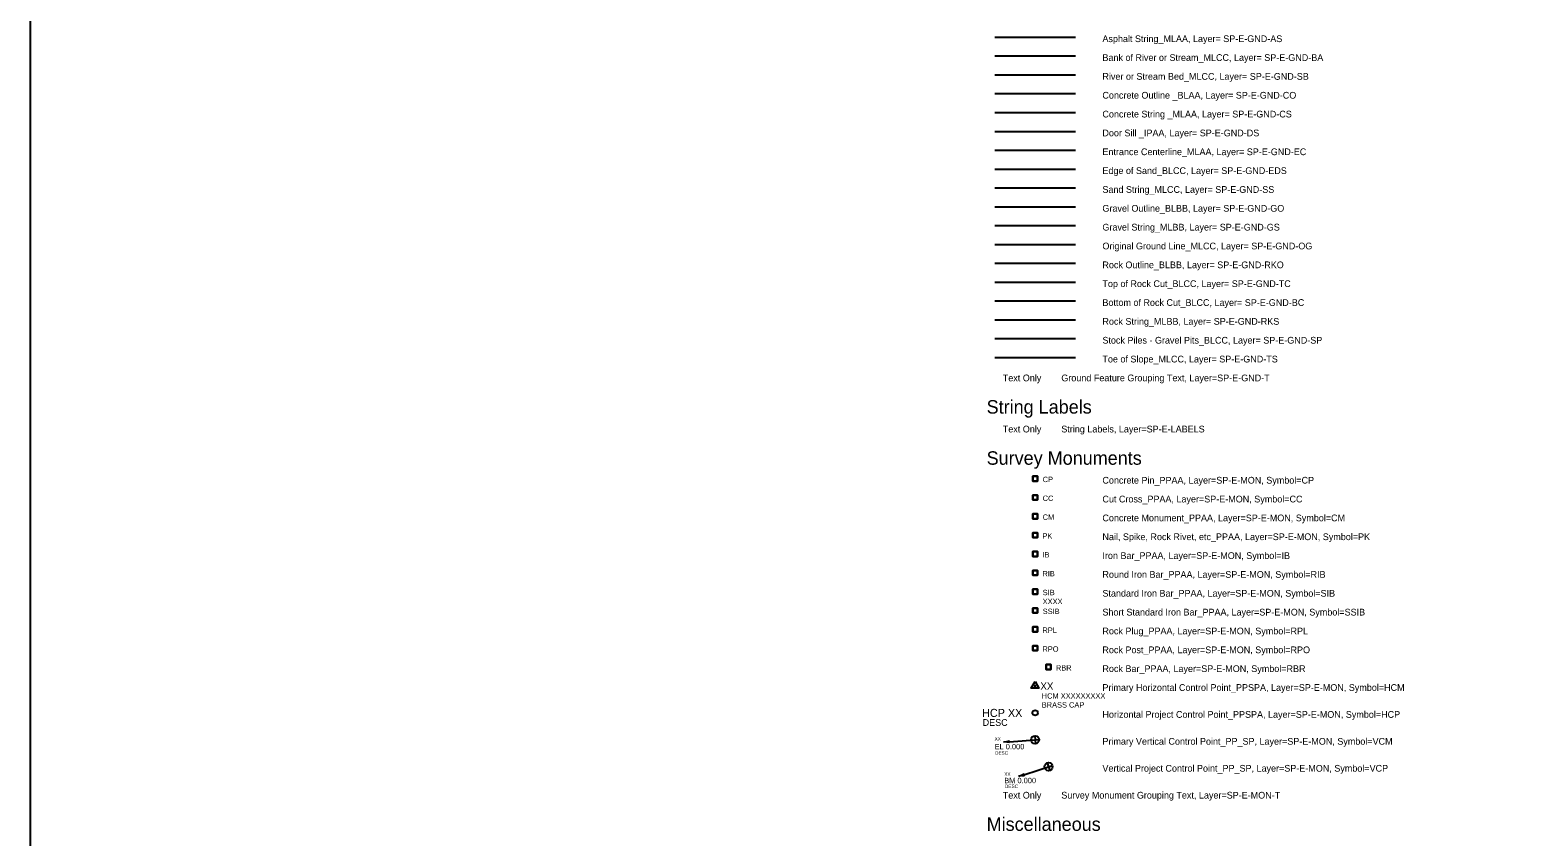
# Model space of a CAD drawing. Extents: x 500528 to 502626, y 4210261 to 4212624.
# Drawn here: x 500528 to 501088, y 4211729 to 4212028 of the extents above; entities that cross this region are included whole.
import ezdxf

# ---------------------------------------------------------------- set-up
doc = ezdxf.new("R2010")
doc.units = 0
for name, color, linetype in [('Default', 7, 'Continuous'), ('SP-E-GND-AS', 7, 'Continuous'), ('SP-E-GND-BA', 7, 'Continuous'), ('SP-E-GND-BC', 7, 'Continuous'), ('SP-E-GND-CO', 7, 'Continuous'), ('SP-E-GND-CS', 7, 'Continuous'), ('SP-E-GND-DS', 7, 'Continuous'), ('SP-E-GND-EC', 7, 'Continuous'), ('SP-E-GND-EDS', 7, 'Continuous'), ('SP-E-GND-GO', 7, 'Continuous'), ('SP-E-GND-GS', 7, 'Continuous'), ('SP-E-GND-OG', 7, 'Continuous'), ('SP-E-GND-RKO', 7, 'Continuous'), ('SP-E-GND-RKS', 7, 'Continuous'), ('SP-E-GND-SB', 7, 'Continuous'), ('SP-E-GND-SP', 7, 'Continuous'), ('SP-E-GND-SS', 7, 'Continuous'), ('SP-E-GND-T', 7, 'Continuous'), ('SP-E-GND-TC', 7, 'Continuous'), ('SP-E-GND-TS', 7, 'Continuous'), ('SP-E-LABELS', 7, 'Continuous'), ('SP-E-MON', 7, 'Continuous'), ('SP-E-MON-T', 7, 'Continuous')]:
    doc.layers.add(name, color=color, linetype=linetype)

# ---------------------------------------------------------------- blocks, each defined once
blk = doc.blocks.new('CP')
at = {"layer": 'SP-E-MON'}
for points in [[(-0.09, 0.09), (0.09, 0.09), (0.09, -0.09), (-0.09, -0.09), (-0.09, 0.09)], [(0.09, -0.09), (0.09, 0.09), (-0.09, 0.09), (-0.09, -0.09), (0.09, -0.09)]]:
    blk.add_lwpolyline(points, dxfattribs=at)
at = {"layer": 'SP-E-MON-T'}
blk.add_text('CP', height=0.2, dxfattribs=at).set_placement((0.281, -0.13))
blk = doc.blocks.new('CC')
at = {"layer": 'SP-E-MON'}
for points in [[(-0.09, 0.09), (0.09, 0.09), (0.09, -0.09), (-0.09, -0.09), (-0.09, 0.09)], [(0.09, -0.09), (0.09, 0.09), (-0.09, 0.09), (-0.09, -0.09), (0.09, -0.09)]]:
    blk.add_lwpolyline(points, dxfattribs=at)
at = {"layer": 'SP-E-MON-T'}
blk.add_text('CC', height=0.2, dxfattribs=at).set_placement((0.281, -0.13))
blk = doc.blocks.new('CM')
at = {"layer": 'SP-E-MON'}
for points in [[(-0.09, 0.09), (0.09, 0.09), (0.09, -0.09), (-0.09, -0.09), (-0.09, 0.09)], [(0.09, -0.09), (0.09, 0.09), (-0.09, 0.09), (-0.09, -0.09), (0.09, -0.09)]]:
    blk.add_lwpolyline(points, dxfattribs=at)
at = {"layer": 'SP-E-MON-T'}
blk.add_text('CM', height=0.2, dxfattribs=at).set_placement((0.281, -0.13))
blk = doc.blocks.new('PK')
at = {"layer": 'SP-E-MON'}
for points in [[(-0.09, 0.09), (0.09, 0.09), (0.09, -0.09), (-0.09, -0.09), (-0.09, 0.09)], [(0.09, -0.09), (0.09, 0.09), (-0.09, 0.09), (-0.09, -0.09), (0.09, -0.09)]]:
    blk.add_lwpolyline(points, dxfattribs=at)
at = {"layer": 'SP-E-MON-T'}
blk.add_text('PK', height=0.2, dxfattribs=at).set_placement((0.272, -0.13))
blk = doc.blocks.new('IB')
at = {"layer": 'SP-E-MON'}
for points in [[(-0.09, 0.09), (0.09, 0.09), (0.09, -0.09), (-0.09, -0.09), (-0.09, 0.09)], [(0.09, -0.09), (0.09, 0.09), (-0.09, 0.09), (-0.09, -0.09), (0.09, -0.09)]]:
    blk.add_lwpolyline(points, dxfattribs=at)
at = {"layer": 'SP-E-MON-T'}
blk.add_text('IB', height=0.2, dxfattribs=at).set_placement((0.272, -0.13))
blk = doc.blocks.new('RIB')
at = {"layer": 'SP-E-MON'}
for points in [[(-0.09, 0.09), (0.09, 0.09), (0.09, -0.09), (-0.09, -0.09), (-0.09, 0.09)], [(0.09, -0.09), (0.09, 0.09), (-0.09, 0.09), (-0.09, -0.09), (0.09, -0.09)]]:
    blk.add_lwpolyline(points, dxfattribs=at)
at = {"layer": 'SP-E-MON-T'}
blk.add_text('RIB', height=0.2, dxfattribs=at).set_placement((0.272, -0.13))
blk = doc.blocks.new('SIB')
at = {"layer": 'SP-E-MON'}
for points in [[(-0.09, 0.09), (0.09, 0.09), (0.09, -0.09), (-0.09, -0.09), (-0.09, 0.09)], [(0.09, -0.09), (0.09, 0.09), (-0.09, 0.09), (-0.09, -0.09), (0.09, -0.09)]]:
    blk.add_lwpolyline(points, dxfattribs=at)
at = {"layer": 'SP-E-MON-T'}
for s, p in [('SIB', (0.281, -0.13)), ('XXXX', (0.281, -0.463))]:
    blk.add_text(s, height=0.2, dxfattribs=at).set_placement(p)
blk = doc.blocks.new('SSIB')
at = {"layer": 'SP-E-MON'}
for points in [[(-0.09, 0.09), (0.09, 0.09), (0.09, -0.09), (-0.09, -0.09), (-0.09, 0.09)], [(0.09, -0.09), (0.09, 0.09), (-0.09, 0.09), (-0.09, -0.09), (0.09, -0.09)]]:
    blk.add_lwpolyline(points, dxfattribs=at)
at = {"layer": 'SP-E-MON-T'}
blk.add_text('SSIB', height=0.2, dxfattribs=at).set_placement((0.281, -0.13))
blk = doc.blocks.new('RPL')
at = {"layer": 'SP-E-MON'}
for points in [[(-0.09, 0.09), (0.09, 0.09), (0.09, -0.09), (-0.09, -0.09), (-0.09, 0.09)], [(0.09, -0.09), (0.09, 0.09), (-0.09, 0.09), (-0.09, -0.09), (0.09, -0.09)]]:
    blk.add_lwpolyline(points, dxfattribs=at)
at = {"layer": 'SP-E-MON-T'}
blk.add_text('RPL', height=0.2, dxfattribs=at).set_placement((0.272, -0.13))
blk = doc.blocks.new('RPO')
at = {"layer": 'SP-E-MON'}
for points in [[(-0.09, 0.09), (0.09, 0.09), (0.09, -0.09), (-0.09, -0.09), (-0.09, 0.09)], [(0.09, -0.09), (0.09, 0.09), (-0.09, 0.09), (-0.09, -0.09), (0.09, -0.09)]]:
    blk.add_lwpolyline(points, dxfattribs=at)
at = {"layer": 'SP-E-MON-T'}
blk.add_text('RPO', height=0.2, dxfattribs=at).set_placement((0.272, -0.13))
blk = doc.blocks.new('RBR')
at = {"layer": 'SP-E-MON'}
for points in [[(-0.09, 0.09), (0.09, 0.09), (0.09, -0.09), (-0.09, -0.09), (-0.09, 0.09)], [(0.09, -0.09), (0.09, 0.09), (-0.09, 0.09), (-0.09, -0.09), (0.09, -0.09)]]:
    blk.add_lwpolyline(points, dxfattribs=at)
at = {"layer": 'SP-E-MON-T'}
blk.add_text('RBR', height=0.2, dxfattribs=at).set_placement((0.272, -0.13))
blk = doc.blocks.new('HCM')
at = {"layer": 'SP-E-MON'}
for points in [[(0, 0.167), (0.144, -0.083), (-0.144, -0.083), (0, 0.167)], [(0, 0.043), (0, -0.043)], [(-0.04, 0), (0.04, 0)]]:
    blk.add_lwpolyline(points, dxfattribs=at)
at = {"layer": 'SP-E-MON-T'}
for s, height, p in [('XX', 0.27, (0.197, -0.142)), ('HCM XXXXXXXXX', 0.2, (0.246, -0.472)), ('BRASS CAP', 0.2, (0.246, -0.806))]:
    blk.add_text(s, height=height, dxfattribs=at).set_placement(p)
blk = doc.blocks.new('HCP')
at = {"layer": 'SP-E-MON'}
blk.add_circle((0, 0), 0.1, dxfattribs=at)
blk.add_circle((0, 0), 0.1, dxfattribs=at)
at = {"layer": 'SP-E-MON-T'}
for s, height, p in [('HCP XX', 0.3, (-1.968, -0.154)), ('DESC', 0.25, (-1.948, -0.484))]:
    blk.add_text(s, height=height, dxfattribs=at).set_placement(p)
blk = doc.blocks.new('VCM')
at = {"layer": 'SP-E-MON'}
for points in [[(-0.96, -0.072), (0.15, 0.011)], [(-0.011, 0.15), (0.011, -0.15)], [(-1.052, -0.079), (-0.958, -0.095), (-0.961, -0.048), (-1.052, -0.079), (-1.177, -0.088)]]:
    blk.add_lwpolyline(points, dxfattribs=at)
blk.add_circle((0, 0), 0.15, dxfattribs=at)
at = {"layer": 'SP-E-MON-T'}
for s, height, p in [('XX', 0.125, (-1.502, -0.03)), ('EL 0.000', 0.2, (-1.505, -0.355)), ('DESC', 0.125, (-1.484, -0.555))]:
    blk.add_text(s, height=height, dxfattribs=at).set_placement(p)
blk = doc.blocks.new('VCP')
at = {"layer": 'SP-E-MON'}
for points in [[(-0.914, -0.302), (0.142, 0.047)], [(-0.047, 0.142), (0.047, -0.142)], [(-1.002, -0.331), (-0.906, -0.324), (-0.921, -0.28), (-1.002, -0.331), (-1.12, -0.371)]]:
    blk.add_lwpolyline(points, dxfattribs=at)
blk.add_circle((0, 0), 0.15, dxfattribs=at)
at = {"layer": 'SP-E-MON-T'}
for s, height, p in [('XX', 0.125, (-1.643, -0.339)), ('BM 0.000', 0.2, (-1.646, -0.614)), ('DESC', 0.13, (-1.626, -0.794))]:
    blk.add_text(s, height=height, dxfattribs=at).set_placement(p)

msp = doc.modelspace()

# ---------------------------------------------------------------- linework, layer by layer
at = {"layer": 'Default'}
msp.add_lwpolyline([(500528.35, 4212623.85), (500528.35, 4210260.5), (502626.48, 4210260.5), (502626.48, 4212623.85), (500528.35, 4212623.85)], dxfattribs=at)
msp.add_lwpolyline([(500528.35, 4210260.5), (502626.48, 4210260.5), (502626.48, 4212623.85), (500528.35, 4212623.85)], close=True, dxfattribs=at)
at = {"layer": 'SP-E-GND-AS'}
msp.add_line((500886.55, 4212025.59), (500916.55, 4212025.59), dxfattribs=at)
at = {"layer": 'SP-E-GND-BA'}
msp.add_line((500886.55, 4212018.59), (500916.55, 4212018.59), dxfattribs=at)
at = {"layer": 'SP-E-GND-BC'}
msp.add_line((500886.55, 4211927.59), (500916.55, 4211927.59), dxfattribs=at)
at = {"layer": 'SP-E-GND-CO'}
msp.add_line((500886.55, 4212004.59), (500916.55, 4212004.59), dxfattribs=at)
at = {"layer": 'SP-E-GND-CS'}
msp.add_line((500886.55, 4211997.59), (500916.55, 4211997.59), dxfattribs=at)
at = {"layer": 'SP-E-GND-DS'}
msp.add_line((500886.55, 4211990.59), (500916.55, 4211990.59), dxfattribs=at)
at = {"layer": 'SP-E-GND-EC'}
msp.add_line((500886.55, 4211983.59), (500916.55, 4211983.59), dxfattribs=at)
at = {"layer": 'SP-E-GND-EDS'}
msp.add_line((500886.55, 4211976.59), (500916.55, 4211976.59), dxfattribs=at)
at = {"layer": 'SP-E-GND-GO'}
msp.add_line((500886.55, 4211962.59), (500916.55, 4211962.59), dxfattribs=at)
at = {"layer": 'SP-E-GND-GS'}
msp.add_line((500886.55, 4211955.59), (500916.55, 4211955.59), dxfattribs=at)
at = {"layer": 'SP-E-GND-OG'}
msp.add_line((500886.55, 4211948.59), (500916.55, 4211948.59), dxfattribs=at)
at = {"layer": 'SP-E-GND-RKO'}
msp.add_line((500886.55, 4211941.59), (500916.55, 4211941.59), dxfattribs=at)
at = {"layer": 'SP-E-GND-RKS'}
msp.add_line((500886.55, 4211920.59), (500916.55, 4211920.59), dxfattribs=at)
at = {"layer": 'SP-E-GND-SB'}
msp.add_line((500886.55, 4212011.59), (500916.55, 4212011.59), dxfattribs=at)
at = {"layer": 'SP-E-GND-SP'}
msp.add_line((500886.55, 4211913.59), (500916.55, 4211913.59), dxfattribs=at)
at = {"layer": 'SP-E-GND-SS'}
msp.add_line((500886.55, 4211969.59), (500916.55, 4211969.59), dxfattribs=at)
at = {"layer": 'SP-E-GND-TC'}
msp.add_line((500886.55, 4211934.59), (500916.55, 4211934.59), dxfattribs=at)
at = {"layer": 'SP-E-GND-TS'}
msp.add_line((500886.55, 4211906.59), (500916.55, 4211906.59), dxfattribs=at)

# ---------------------------------------------------------------- block references
at = {"layer": 'SP-E-MON', "xscale": 10, "yscale": 10}
for name, p in [('CP', (500901.55, 4211861.59)), ('CC', (500901.55, 4211854.59)), ('CM', (500901.55, 4211847.59)), ('PK', (500901.55, 4211840.59)), ('IB', (500901.55, 4211833.59)), ('RIB', (500901.55, 4211826.59)), ('SIB', (500901.55, 4211819.59)), ('SSIB', (500901.55, 4211812.59)), ('RPL', (500901.55, 4211805.59)), ('RPO', (500901.55, 4211798.59)), ('RBR', (500906.55, 4211791.59)), ('HCM', (500901.55, 4211784.59)), ('HCP', (500901.55, 4211774.59)), ('VCM', (500901.55, 4211764.59)), ('VCP', (500906.55, 4211754.59))]:
    msp.add_blockref(name, p, dxfattribs=at)

# ---------------------------------------------------------------- texts
at = {"layer": 'Default'}
for s, p in [('String Labels ', (500883.55, 4211885.74)), ('Survey Monuments ', (500883.55, 4211866.74)), ('Miscellaneous ', (500883.55, 4211730.74))]:
    msp.add_text(s, height=5, dxfattribs=at).set_placement(p)
at = {"layer": 'SP-E-GND-AS'}
msp.add_text('Asphalt String_MLAA, Layer= SP-E-GND-AS ', height=2.5, dxfattribs=at).set_placement((500926.55, 4212023.74))
at = {"layer": 'SP-E-GND-BA'}
msp.add_text('Bank of River or Stream_MLCC, Layer= SP-E-GND-BA ', height=2.5, dxfattribs=at).set_placement((500926.55, 4212016.74))
at = {"layer": 'SP-E-GND-BC'}
msp.add_text('Bottom of Rock Cut_BLCC, Layer= SP-E-GND-BC ', height=2.5, dxfattribs=at).set_placement((500926.55, 4211925.74))
at = {"layer": 'SP-E-GND-CO'}
msp.add_text('Concrete Outline _BLAA, Layer= SP-E-GND-CO ', height=2.5, dxfattribs=at).set_placement((500926.55, 4212002.74))
at = {"layer": 'SP-E-GND-CS'}
msp.add_text('Concrete String _MLAA, Layer= SP-E-GND-CS ', height=2.5, dxfattribs=at).set_placement((500926.55, 4211995.74))
at = {"layer": 'SP-E-GND-DS'}
msp.add_text('Door Sill _IPAA, Layer= SP-E-GND-DS ', height=2.5, dxfattribs=at).set_placement((500926.55, 4211988.74))
at = {"layer": 'SP-E-GND-EC'}
msp.add_text('Entrance Centerline_MLAA, Layer= SP-E-GND-EC ', height=2.5, dxfattribs=at).set_placement((500926.55, 4211981.74))
at = {"layer": 'SP-E-GND-EDS'}
msp.add_text('Edge of Sand_BLCC, Layer= SP-E-GND-EDS ', height=2.5, dxfattribs=at).set_placement((500926.55, 4211974.74))
at = {"layer": 'SP-E-GND-GO'}
msp.add_text('Gravel Outline_BLBB, Layer= SP-E-GND-GO ', height=2.5, dxfattribs=at).set_placement((500926.55, 4211960.74))
at = {"layer": 'SP-E-GND-GS'}
msp.add_text('Gravel String_MLBB, Layer= SP-E-GND-GS ', height=2.5, dxfattribs=at).set_placement((500926.55, 4211953.74))
at = {"layer": 'SP-E-GND-OG'}
msp.add_text('Original Ground Line_MLCC, Layer= SP-E-GND-OG ', height=2.5, dxfattribs=at).set_placement((500926.55, 4211946.74))
at = {"layer": 'SP-E-GND-RKO'}
msp.add_text('Rock Outline_BLBB, Layer= SP-E-GND-RKO ', height=2.5, dxfattribs=at).set_placement((500926.55, 4211939.74))
at = {"layer": 'SP-E-GND-RKS'}
msp.add_text('Rock String_MLBB, Layer= SP-E-GND-RKS ', height=2.5, dxfattribs=at).set_placement((500926.55, 4211918.74))
at = {"layer": 'SP-E-GND-SB'}
msp.add_text('River or Stream Bed_MLCC, Layer= SP-E-GND-SB ', height=2.5, dxfattribs=at).set_placement((500926.55, 4212009.74))
at = {"layer": 'SP-E-GND-SP'}
msp.add_text('Stock Piles - Gravel Pits_BLCC, Layer= SP-E-GND-SP ', height=2.5, dxfattribs=at).set_placement((500926.55, 4211911.74))
at = {"layer": 'SP-E-GND-SS'}
msp.add_text('Sand String_MLCC, Layer= SP-E-GND-SS ', height=2.5, dxfattribs=at).set_placement((500926.55, 4211967.74))
at = {"layer": 'SP-E-GND-T'}
msp.add_text('Text Only        Ground Feature Grouping Text, Layer=SP-E-GND-T', height=2.5, dxfattribs=at).set_placement((500889.55, 4211897.74))
at = {"layer": 'SP-E-GND-TC'}
msp.add_text('Top of Rock Cut_BLCC, Layer= SP-E-GND-TC ', height=2.5, dxfattribs=at).set_placement((500926.55, 4211932.74))
at = {"layer": 'SP-E-GND-TS'}
msp.add_text('Toe of Slope_MLCC, Layer= SP-E-GND-TS ', height=2.5, dxfattribs=at).set_placement((500926.55, 4211904.74))
at = {"layer": 'SP-E-LABELS'}
msp.add_text('Text Only        String Labels, Layer=SP-E-LABELS', height=2.5, dxfattribs=at).set_placement((500889.55, 4211878.74))
at = {"layer": 'SP-E-MON'}
for s, p in [('Concrete Pin_PPAA, Layer=SP-E-MON, Symbol=CP ', (500926.55, 4211859.74)), ('Cut Cross_PPAA, Layer=SP-E-MON, Symbol=CC ', (500926.55, 4211852.74)), ('Concrete Monument_PPAA, Layer=SP-E-MON, Symbol=CM ', (500926.55, 4211845.74)), ('Nail, Spike, Rock Rivet, etc_PPAA, Layer=SP-E-MON, Symbol=PK ', (500926.55, 4211838.74)), ('Iron Bar_PPAA, Layer=SP-E-MON, Symbol=IB ', (500926.55, 4211831.74)), ('Round Iron Bar_PPAA, Layer=SP-E-MON, Symbol=RIB ', (500926.55, 4211824.74)), ('Standard Iron Bar_PPAA, Layer=SP-E-MON, Symbol=SIB ', (500926.55, 4211817.74)), ('Short Standard Iron Bar_PPAA, Layer=SP-E-MON, Symbol=SSIB ', (500926.55, 4211810.74)), ('Rock Plug_PPAA, Layer=SP-E-MON, Symbol=RPL ', (500926.55, 4211803.74)), ('Rock Post_PPAA, Layer=SP-E-MON, Symbol=RPO ', (500926.55, 4211796.74)), ('Rock Bar_PPAA, Layer=SP-E-MON, Symbol=RBR ', (500926.55, 4211789.74)), ('Primary Horizontal Control Point_PPSPA, Layer=SP-E-MON, Symbol=HCM ', (500926.55, 4211782.74)), ('Horizontal Project Control Point_PPSPA, Layer=SP-E-MON, Symbol=HCP ', (500926.55, 4211772.74)), ('Primary Vertical Control Point_PP_SP, Layer=SP-E-MON, Symbol=VCM ', (500926.55, 4211762.74)), ('Vertical Project Control Point_PP_SP, Layer=SP-E-MON, Symbol=VCP ', (500926.55, 4211752.74))]:
    msp.add_text(s, height=2.5, dxfattribs=at).set_placement(p)
at = {"layer": 'SP-E-MON-T'}
msp.add_text('Text Only        Survey Monument Grouping Text, Layer=SP-E-MON-T', height=2.5, dxfattribs=at).set_placement((500889.55, 4211742.74))

doc.saveas('drawing.dxf')
